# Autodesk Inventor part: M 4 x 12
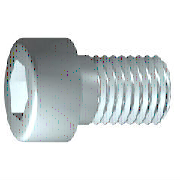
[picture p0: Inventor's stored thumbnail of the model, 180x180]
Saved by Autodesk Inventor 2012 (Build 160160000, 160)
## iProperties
IsCustomPart: 0
Created: 2009-02
Part Number: M 4 x 12
Material: 강, 연강
Description: 6각머리 태핑 나사
Document SubType Name: Modeling
Standard: KS B 1003
Designer: KYOUNG IL JANG
Standards Organization: KS
Language: ko-KR
Size Designation: M 4 x 12
Categories: <MemberInstance><Categories><Category DisplayName="조임쇠" InternalName="e4da775c-781d-43d5-af7c-5136215cf5a6" Mnemonic="FSTN"><Category DisplayName="볼트" InternalN
Density: 7.86 g/cm^3
Mass: 2.23465 g
Surface Area: 3.30853 cm^2
Volume: 0.284306 cm^3
Author: KYOUNG IL JANG
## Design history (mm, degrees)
revolve "본체" stored, may be unused: angle "d10" = 90 deg
sketch "스케치2"
  geometry: L1 (0, -4.9)-(0, 4.9) reference; L2 (-4.9, 0)-(4.9, 0) reference; L3 (1.732, 0)-(0.866, -1.5); L4 (0.866, -1.5)-(-0.866, -1.5); L5 (-0.866, -1.5)-(-1.732, 0); L6 (-1.732, 0)-(-0.866, 1.5); L7 (-0.866, 1.5)-(0.866, 1.5); L8 (0.866, 1.5)-(1.732, 0); 2 further points
  constraints: 12 end point, 1 coincident, 1 horizontal alignment, 1 point on line, 12 other
extrude "슬롯" join sketch "스케치2" stored distance "d11" = 10; taper "d12" = 0 deg
workplane "Work Plane1"
fillet "Fillet2" dims "d30" = 0.1 (= R)
body "Solid1"
fillet "모깎기1" dims "d17" = 0.4 (= RR)
feature "스레드" dims "d13" = 10.25 (= GEL), "d14" = 0
chamfer "모따기1" distance "d15" = 0.42941 (= -0.5 x SPD + 0.5 x GD); stored, may be unused: second distance "d16" = 0.42941 (= GUL), angle "d27" = 45 deg
sketch "스케치1"
  geometry: L1 (-1, 0)-(12, 0); L2 (12, 0)-(12, 2); L3 (12, 2)-(1.75, 2); L4 (1.75, 2)-(1.32, 2); L5 (1.32, 2)-(0, 2); L6 (0, 2)-(0, 3.5); L7 (0, 3.5)-(-4, 3.5); L8 (-4, 3.5)-(-4, 1.732); L9 (-4, 1.732)-(-2, 1.732); L10 (-2, 1.732)-(-1, 0); L11 (-7.2, 0)-(15.2, 0) reference; L12 (0, -0.7)-(0, 4.2) reference; L13 (1.75, 2)-(0, 2)
  constraints: 22 end point, 6 parallel, 2 collinear, 2 perpendicular, 1 horizontal, 1 point on line
  dimensions: "d1" = 10.25 distance from line of L3.end L2 (= GEL); "d2" = 0.42952 distance of L4.end L3.end (computed from GAL); "d3" = 4 distance between parallel lines of L8 L6 (= KOH); "d4" = 2 distance of L8.end L9.end (= INTI); "d5" = 60 deg angle of L10 L1; "d6" = 4 diameter of L3 L1 (= GD); "d7" = 4 diameter of L5 L1 (= BDM); "d8" = 3.4641 diameter of L9 L1 (= 1.1547 x SW); "d9" = 7 diameter of L7 L1 (= KOD); "d26" = 12 distance between parallel lines of L12 L2 (= NLG)
other parameters: "GD" = 4 (= NND) [user parameter; used in 2 equation terms], "NLG" = 12 [user parameter; used in 1 equation term], "GEL" = 10.25 [user parameter; used in 2 equation terms], "KOD" = 7 [user parameter; used in 1 equation term], "KOH" = 4 [user parameter; used in 1 equation term], "INTI" = 2 [user parameter; used in 1 equation term], "GAL" = 0.42941 (= 0.61345 x PTC) [user parameter; used in 1 equation term], "GUL" = 0.42941 (= 0.61345 x PTC) [user parameter; used in 1 equation term], "BDM" = 4 (= NND) [user parameter; used in 1 equation term], "SW" = 3 [user parameter; used in 2 equation terms], "RR" = 0.4 [user parameter; used in 1 equation term], "SPD" = 3.14117 (= NND - 1.2269 x PTC) [user parameter; used in 1 equation term], "d19" = 0, "d28" = 0, "d29" = 0, "R" = 0.1 [user parameter; used in 1 equation term], "PHH" = 0.2 [user parameter], "GD1" = 3.14117 (= THREADDIA - 1.2269 x PTC) [user parameter], "THREADDIA" = 4 [user parameter; used in 1 equation term], "FAWI" = 45 deg [user parameter], "TPU" = 14.28571 (computed from PTC) [user parameter], "PTC" = 0.7 [user parameter; used in 5 equation terms], "NND" = 4 [user parameter; used in 3 equation terms], "TOA" = 30 deg [user parameter], "E0" = 3.465 (= 1.155 x SW) [user parameter]
